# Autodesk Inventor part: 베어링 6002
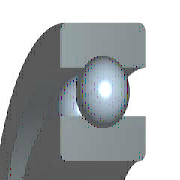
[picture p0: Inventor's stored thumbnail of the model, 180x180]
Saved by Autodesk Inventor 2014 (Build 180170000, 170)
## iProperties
Created: 2012-02
Part Number: 베어링 6002
Material: 강철, 연강
Description: 깊은 그루브 볼 베어링
Document SubType Name: Modeling
Standard: KS B 2023
Designer: mduedu
Standards Organization: KS
Language: ko-KR
Size Designation: 6002 - 15 x 32 x 9
Categories: <MemberInstance><Categories><Category DisplayName="샤프트 부품" InternalName="7f7aeb1f-a693-4053-b835-cee3144e0d98" Mnemonic="SHFT"><Category DisplayName="베어링" Inter
Density: 1 g/cm^3
Appearance: 노란색
IsCustomPart: 1
Author: mduedu
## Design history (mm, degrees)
sketch "스케치" dims "d0" = 4.42 (= -0.26 x WD + 0.26 x BD)
  geometry: L1 (2.29, 11.75)-(6.71, 11.75); L2 (4.5, 11.75)-(4.5, 9.54); L3 (4.5, 11.75)-(4.5, 13.96); L4 (2.858, 10.271)-(0, 10.271); L5 (0, 7.5)-(9, 7.5); L6 (2.858, 13.229)-(0, 13.229); L7 (0, 16)-(9, 16); L8 (9, 7.5)-(9, 10.271); L9 (6.142, 10.271)-(9, 10.271); L10 (6.142, 13.229)-(9, 13.229); L11 (9, 16)-(9, 13.229); L12 (-1.4, 0)-(8.4, 0) reference; L13 (0, -0.3)-(0, 5.3) reference
  constraints: 22 end point, 4 point on line, 2 collinear, 2 perpendicular, 2 symmetric about line, 1 midpoint, 1 parallel, 14 other
  dimensions: "d9" = 15 diameter of L5 L12 (= WD); "d11" = 32 diameter of L7 L12 (= BD); "d12" = 9 distance between parallel lines of L8 L13 (= KB); "d13" = 20.542 diameter of L9 L12 (= 0.326 x BD + 0.674 x WD)
revolve "본체" stored, may be unused: angle "d6" = 90 deg
revolve "볼" stored, may be unused: angle "d7" = 90 deg
pattern_circular "IDS_ARRAYBALL[SIMPL:T]" dims angle "d3" = 360 deg
body "Solid1"
fillet "모깎기1" dims "d1" = 0.3 (= KRS)
other parameters: "WD" = 15 [user parameter; used in 5 equation terms], "BD" = 32 [user parameter; used in 5 equation terms], "KB" = 9 [user parameter; used in 1 equation term], "KRS" = 0.3 [user parameter; used in 1 equation term], "d4" = 0, "d5" = 0, "d8" = 0, "d14" = 0, "d15" = 0, "BBA" = 0 [user parameter], "BC0" = 2850000 [user parameter], "BC" = 5590000 [user parameter], "BR" = 16 (= 0.5 x BD) [user parameter], "WR" = 7.5 (= 0.5 x WD) [user parameter]
